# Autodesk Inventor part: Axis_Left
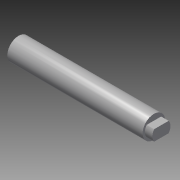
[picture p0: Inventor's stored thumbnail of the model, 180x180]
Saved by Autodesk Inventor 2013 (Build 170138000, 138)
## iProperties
Created: 2006-03
Part Number: Axis_Left
Document SubType Name: Modeling
Designer: debonom
Material: Stainless Steel, 440C
Mass: 126.377 g
Surface Area: 47.6763 cm^2
Volume: 16.3066 cm^3
Density: 7.75 g/cm^3
Author: debonom
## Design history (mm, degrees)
sketch "Sketch1"
  geometry: L1 (-4.823, 3.575)-(4.823, 3.575); L2 (4.823, 3.575)-(4.823, -3.575); L3 (4.823, -3.575)-(-4.822, -3.575); L4 (-4.822, -3.575)-(-4.823, 3.575); L5 (-4.823, 3.575)-(4.823, -3.575); L6 (-8.405, 0)-(8.405, 0) reference; A1 r 6 centre (-0.004, 0) between (-4.823, 3.575) and (-4.822, -3.575); A2 r 6 centre (0.004, 0) between (4.823, -3.575) and (4.823, 3.575); 2 further points
  constraints: 10 end point, 4 point on circle, 2 centre point, 2 parallel, 2 point on line, 1 coincident, 1 equal radius, 1 horizontal, 1 midpoint, 1 perpendicular
  dimensions: "d0" = 9.645 distance of L2.end L3.end; "d1" = 7.15 distance of L3.end L1.start; "d2" = 6 radius of A1
extrude "Extrusion1" new body sketch "Sketch1" distance "d3" = 5; taper "d4" = 0 deg
sketch "Sketch2"
  geometry: C1 r 7.5 at (0, 0); 1 further point
  constraints: 1 centre point, 1 coincident
  dimensions: "d5" = 15 diameter of C1
extrude "Extrusion2" join sketch "Sketch2" distance "d6" = 90; taper "d7" = 0 deg
body "Solid1"
